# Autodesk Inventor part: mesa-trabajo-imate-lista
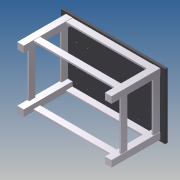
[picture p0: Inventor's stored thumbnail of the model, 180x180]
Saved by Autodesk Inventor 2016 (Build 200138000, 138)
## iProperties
Created: 2012-05
Part Number: mesa-trabajo-imate-lista
Material: Generic
Document SubType Name: Modeling
Designer: julian.chica
Density: 1 g/cm^3
Appearance: Default
Author: julian.chica
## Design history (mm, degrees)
sketch "Sketch2"
  geometry: L1 (-800, 500)-(800, 500); L2 (800, 500)-(800, -500); L3 (800, -500)-(-800, -500); L4 (-800, -500)-(-800, 500); 3 further points
  constraints: 8 end point, 2 midpoint, 2 parallel, 1 horizontal, 1 horizontal alignment, 1 perpendicular, 1 vertical alignment
  dimensions: "d0" = 1600 distance of L2.end L3.end; "d1" = 1000 distance of L1.end L2.end
extrude "Extrusion1" new body sketch "Sketch2" distance "d2" = 38.1; taper "d3" = 0 deg
sketch "Sketch3"
  geometry: L1 (800, 500)-(800, -500) reference; L2 (-800, 500)-(800, 500) reference; L3 (-800, -500)-(-800, 500) reference; L4 (800, -500)-(-800, -500) reference; L5 (720, 470)-(720, -470); L6 (720, -470)-(-720, -470); L7 (-720, -470)-(-720, 470); L8 (-720, 470)-(720, 470); L9 (694.6, 444.6)-(694.6, -444.6); L10 (694.6, -444.6)-(-694.6, -444.6); L11 (-694.6, -444.6)-(-694.6, 444.6); L12 (-694.6, 444.6)-(694.6, 444.6); 1 further point
  constraints: 16 end point, 3 other
  dimensions: "d4" = 25.4 distance between parallel lines of L12 L8; "d8" = 30 distance between parallel lines of L2 L8; "d9" = 30 distance between parallel lines of L4 L6; "d10" = 80 distance between parallel lines of L1 L5; "d11" = 80 distance between parallel lines of L3 L7
extrude "Extrusion2" join sketch "Sketch3" distance "d6" = 100; taper "d7" = 0 deg
sketch "Sketch4"
  geometry: L1 (-720, 470)-(-630, 470); L2 (-630, 470)-(-630, 380); L3 (-630, 380)-(-720, 380); L4 (-720, 380)-(-720, 470); L5 (-725, 375)-(-625, 375); L6 (-625, 375)-(-625, 475); L7 (-625, 475)-(-725, 475); L8 (-725, 475)-(-725, 375); L9 (625, 375)-(725, 375); L10 (725, 375)-(725, 475); L11 (725, 475)-(625, 475); L12 (625, 475)-(625, 375); L13 (-725, -475)-(-625, -475); L14 (-625, -475)-(-625, -375); L15 (-625, -375)-(-725, -375); L16 (-725, -375)-(-725, -475); L17 (625, -475)-(725, -475); L18 (725, -475)-(725, -375); L19 (725, -375)-(625, -375); L20 (625, -375)-(625, -475); 3 further points
  constraints: 40 end point, 4 parallel, 2 horizontal, 2 perpendicular, 1 vertical, 27 other
  dimensions: "d12" = 90 distance of L2.end L3.end; "d13" = 90 distance of L1.end L2.end; "d14" = 5 distance between parallel lines of L3 L5; "d17" = 1350 distance of L5.start L9.start; "d20" = 850 distance of L5.start L13.start
extrude "Extrusion3" join sketch "Sketch4" distance "d23" = 750; taper "d24" = 0 deg
pattern_linear "Rectangular Pattern1" dims "d27" = 500
sketch "Sketch5"
  geometry: L1 (800, -500)-(-800, -500) reference; L2 (800, 500)-(800, -500) reference; 5 further points
  constraints: 2 horizontal alignment, 2 vertical alignment
  dimensions: "d28" = 160 distance of point (550, -380) point (390, -380); "d29" = 205 distance of point (390, -380) point (390, -175); "d30" = 120 distance from line of L1 point (550, -380); "d31" = 250 distance from line of L2 point (550, -380)
hole "Hole1" sketch "Sketch5" at (390, -175), (550, -175), (550, -380), (390, -380) diameter "d32" = 9; stored, may be unused: countersink angle "d36" = 90 deg, drill point angle "d38" = 118 deg; dims "d33" = 6, "d34" = 4, "d35" = 2, "d37" = 8
pattern_linear "Rectangular Pattern2" dims "d41" = 950
body "Solid1"
